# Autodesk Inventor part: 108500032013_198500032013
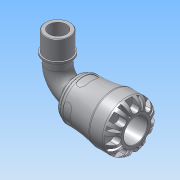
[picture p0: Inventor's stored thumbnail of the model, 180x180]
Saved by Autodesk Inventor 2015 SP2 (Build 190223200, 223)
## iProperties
Created: 2016-12
Part Number: 108500032013_198500032013
Material: PVC-Piping
Description: PLASSON 90° ELBOW WITH THREADED MALE OFFTAKE 32X1.1/4" SERIES 1
Document SubType Name: Modeling
Designer: KIM
Mass: 664.223 g
Surface Area: 733.008 cm^2
Volume: 474.445 cm^3
Density: 1.4 g/cm^3
Appearance: Smooth - White
Author: KIM
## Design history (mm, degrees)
derived "1085.ipt"
feature "Solid1::1085.ipt"
tag "TaggingFeature1"
body "Solid1"
other parameters: "d1" = 22.26, "d2" = 32, "d4" = 58, "d8" = 49.3, "d13" = 7.2, "d14" = 7.2, "d15" = 0, "d17" = 360 deg, "d19" = 8 deg, "d20" = 0.64, "d21" = 0.64, "d22" = 8 deg, "d24" = 0, "d26" = 360 deg, "d33" = 5.8, "d43" = 45.24, "d51" = 0.58, "d54" = 11.2, "d55" = 7.04, "d57" = 14.112, "d58" = 0, "d74" = 0, "d78" = 53, "d82" = 0.64, "d115" = 360 deg, "d207" = 90 deg, "d228" = 9.52, "d247" = 1.16, "d248" = 3.18, "d268" = 27.115, "d269" = 3.18, "d270" = 81, "d276" = 41.91, "d277" = 21, "d278" = 46.101, "d279" = 54, "d280" = 23.1, "d281" = 6.2865, "d283" = 37.719, "d286" = 0, "d287" = 0, "d288" = 29.337, "d290" = 3.7605, "d292" = 30 deg, "d_" = 32, "E_" = 58, "l_" = 53, "A_" = 81, "A_1" = 54, "l_2" = 21, "R_" = 41.91, "d9" = 9, "d11" = 58, "d289" = 29.337
